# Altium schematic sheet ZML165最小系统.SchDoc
size A4; CheckedBy: <审核日期>; Author: <设计人员>; CompanyName: 广州立功科技股份有限公司; DocumentNumber: 1; SheetNumber: 1; SheetTotal: 1; PageSetup: Record=PageOptions|CenterHorizontal=True|CenterVertical=True|PrintScale=1.00|XCorrection=1.00|YCorrection=1.00|PrintKind=0|BorderSize=5000000|LeftOffset=0|BottomOffset=0|Orientation=2|PaperLength=1000|PaperWidth=1000|Scale=100|PaperSource=7|PrintQuality=600|MediaType=1|DitherType=10|PaperKind=A4|PrintScaleMode=1; DesignDate: <设计日期>; CheckDate: <审核人员>; SheetName: <图纸名称>; SheetVersion: <图纸版本>; SheetDescription: <图纸描述>
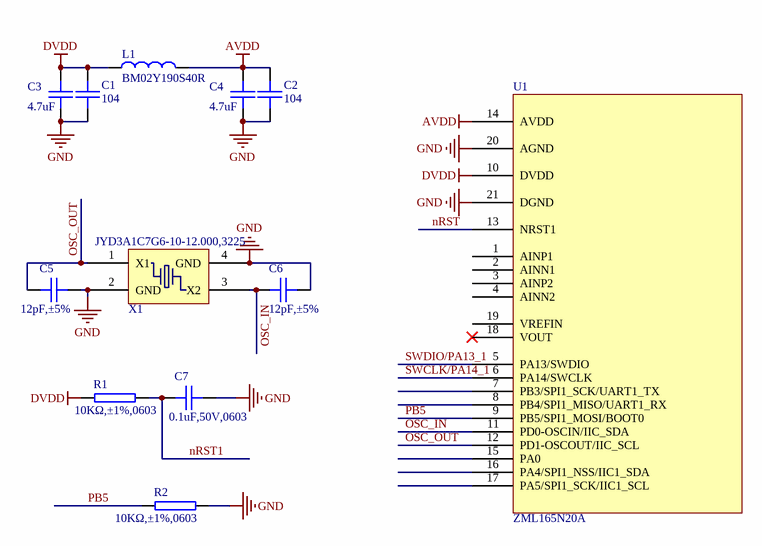
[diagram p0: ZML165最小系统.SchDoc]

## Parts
C1  104  [0603C]
C2  104  [0603C]
C3  4.7uF  [0603C]
C4  4.7uF  [0603C]
C5  12pF,±5%  [0402C]
C6  12pF,±5%  [0402C]
C7  0.1uF,50V,0603  [0603C]
L1  BM02Y190S40R  [0402RL]
R1  10KΩ,±1%,0603  [0603R]
R2  10KΩ,±1%,0603  [0603R]
U1  ZML165N20A
X1  JYD3A1C7G6-10-12.000,3225  [OSCCC250X320X80-4N]

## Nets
AVDD: C2.1 C4.1 L1.2 U1.14(AVDD)
DVDD: C1.1 C3.1 L1.1 R1.1 U1.10(DVDD)
GND: C1.2 C2.2 C3.2 C4.2 C5.1 C6.2 C7.2 R2.2 U1.20(AGND) U1.21(DGND) X1.2(GND) X1.4(GND)
nRST: U1.13(NRST1)
nRST1: C7.1 R1.2
OSC_IN: C6.1 U1.11(PD0-OSCIN/IIC_SDA) X1.3(X2)
OSC_OUT: C5.2 U1.12(PD1-OSCOUT/IIC_SCL) X1.1(X1)
PB5: R2.1 U1.9(PB5/SPI1_MOSI/BOOT0)
SWCLK/PA14_1: U1.6(PA14/SWCLK)
SWDIO/PA13_1: U1.5(PA13/SWDIO)

Not connected (* = marked no-connect by the designer): U1 1(AINP1) 2(AINN1) 3(AINP2) 4(AINN2) 7(PB3/SPI1_SCK/UART1_TX) 8(PB4/SPI1_MISO/UART1_RX) 15(PA0) 16(PA4/SPI1_NSS/IIC1_SDA) 17(PA5/SPI1_SCK/IIC1_SCL) 18(VOUT)* 19(VREFIN)

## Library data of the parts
C1 C2 = 1.02.01.0072: C1608X7R1H104KT000N，104，±10%，50V，X7R,TDK,0603,RoHS; 名称: 电容; 封装: 0603; 贴片和直插: SMT; PCB备注: 151110lmd; 器件优选方案: 正常状态，可以选用
C3 C4 = 02.01.00449: GRM188R61C475KAAJD,4.7uF,16V,±15%,X5R,0603,muRata; 名称: 电容; 封装: 0603; 贴片和直插: SMT; PCB备注: 190510CZY; 器件优选方案: 通用物料
C5 C6 = 1.02.17.0018: GRM1555C1H120JA01D,12pF,±5%,50V,C0G,0402,muRata,RoHS; 名称: 电容; 封装: 0402; 设备封装名称: C0402_12PF_COG_50V_5%; 贴片和直插: SMT; 器件优选方案: 正常状态，可以选用
C7 = 02.01.00015: C1608X7R1H104KT000N,0603,TDK,0.1uF,X7R,±10%,50V,; 旧物料代码: 1.02.01.0072; 名称: 电容; 封装: 0603; 贴片和直插: SMT; PCB备注: 151110lmd; 器件优选方案: 推荐使用
L1 = 1.03.03.0022: BM02Y190S40R,0402,丰晶,RoHS; 名称: 磁珠; 封装: 0402; 贴片和直插: SMT; 器件优选方案: 正常状态，可以选用
R1 R2 = 01.01.00047: RTT031002FTP,0603,RALEC,10KΩ,±1%,1/10W,; 旧物料代码: 1.01.01.0052; 名称: 电阻; 封装: 0603; 贴片和直插: SMT; 器件优选方案: 通用物料
X1 = 12.02.00162: JYD3A1C7G6-10-12.000,3225,JYEG,12MHz,±10ppm,10pF,-40~85℃,; 旧物料代码: 1.07.01.0032; 名称: 晶体; 封装: SMT; PCB备注: 151229lmd171128ZW; 器件优选方案: 通用物料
